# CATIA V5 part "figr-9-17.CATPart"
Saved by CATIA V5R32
Part number: Part1
Bounding box of the stored display mesh (mm): x -77.304 to 77.304, y -77.304 to 125.507, z 0 to 125
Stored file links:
  D:\PROJECTS\Project 2022\CATIA V5 6R 2022\Resources\Part Files\c09_catia_v5_6r2022_prt\c09_catia_v5_6r2022_prt\figr-9-17.CATPart
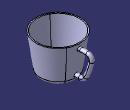
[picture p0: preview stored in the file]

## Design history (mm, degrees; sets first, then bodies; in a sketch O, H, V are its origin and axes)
Set1
  Plane1: type Normal, Curve Sketch3, RefPoint vertex of Sketch3
Body1 (main body)
  Sketch1 on yz-plane, origin (0, 0, 0), H (0, 1, 0), V (0, 0, 1)
    line L1 (0, 0) -> (60, 0)
    point P1 (60, 0)
    point P2 (60, 0)
    line L2 (60, 0) -> (77.5, 125)
    point P3 (77.5, 125)
    line L3 (77.5, 125) -> (0, 125)
    point P4 (0, 125)
    line L4 (0, 125) -> (0, 0)
    axis line L5 (0, 150.2858) -> (0, -31.0593)
    point P5 (0, 150.2858)
    radius about axis P1 L5 = 60
    radius about axis P3 L5 = 77.5
    distance L3 L1 = 125
    horizontal: L1 H, L3 H
    coincidence: P4 V, P2 P1, P5 V
    vertical: L4 V, L5 V
  Shaft1: profile Sketch1, axis Sketch1.L5, angle 360
  Fillet1: radius 15, on edge [face of Shaft1 | face of Shaft1]
  Shell1: ExtOffset 0, Face face of Shaft1, IntOffset 4
  Sketch2 on Plane1, origin (0, 62.9841, 0), H (-1, 0, 0), V (0, 0, 1)
    circle A1 centre (0, 22.002) radius 7.5
    reference projected point E1 (0, 22.002) from vertex of Sketch3
    radius A1 = 7.5
    concentricity: A1 E1
  Sketch3 on yz-plane, origin (0, 0, 0), H (0, 1, 0), V (0, 0, 1)
    line L1 (62.9841, 22.002) -> (78.2172, 22.002)
    arc A1 centre (78.2172, 44.1133) radius 22.1113 from (78.2172, 22.002) to (97.9307, 34.0988) ccw
    arc A2 centre (-112.3295, 140.9107) radius 235.8349 from (97.9307, 34.0988) to (117.8681, 89.6549) ccw
    arc A3 centre (104.0328, 92.7355) radius 14.1742 from (117.8681, 89.6549) to (104.4272, 106.9041) ccw
    arc A4 centre (93.6744, -279.4123) radius 386.4661 from (104.4272, 106.9041) to (82.9216, 106.9041) ccw
    horizontal: L1 H
    tangency: A1 L1, A2 A1, A3 A2, A4 A3
  Rib1: profile Sketch2, centre curve Sketch3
